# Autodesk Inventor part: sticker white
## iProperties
Shininess: 64.0
Length Units: 11269
Angle Units: 11279
Time Units: 11290
Mass Units: 11283
Length Display Precision: 3
Angle Display Precision: 2
Compacted: True
Part Number: sticker white
Document SubType Name: Modeling
Created: 2004-10
Material: Standard
Designer: W. Holzwarth
Manufacturer: Standard
Standards Organization: Custom
Density: 0.0
Volumn: 0.0
Area: 0.0
PropertySet Name: Model Information
Control State: 0
Master: False
Checked Out: False
Author: W. Holzwarth
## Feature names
1. Basis1
